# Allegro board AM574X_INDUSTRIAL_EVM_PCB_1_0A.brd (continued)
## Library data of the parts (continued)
C473-C475 = 1C_47uFCapacitor10V10%smd2917: User Part Number: P/N*; Tolerance: TOL*
C476 = 1C_2.2uFCapacitor10V20%smd0402: Tolerance: TOLERANCE; User Part Number: USERPART#
C554 C555 = C0402C104J4RACTU: Tolerance: TOLERANCE; signal model: 1C_0.1UFCAPACITOR16V10%0402_SM-_0.1uF
D1 = 1E_Diode_15ARect_rev45V
D2 = SMCJ5.0A
D3 D4 = Diode200mA250V_0
D5-D13 = 5988170107F
D14 D15 = Diode_500mA20V
D16-D19 D22 D23 = SM1210RGB
D20 = PMEG2010BELD,315
D24 D25 = TLVH431_0
F1 = 1P_Fuse_0
FB1-FB8 = HF70ACB201209-T
FB9-FB11 = MPZ1608S221ATA00
FB12 FB13 FB19 = 1L_FerBead_0
J1 = 2J_Conn_PwrJack_RAPC712
J1_1 = 2H_Header_4x1_female
J2 = 2C_Conn_LeadScrewDown_2pin
J3 J5 J6 J8 = 2J_ConnectorRJ45_10_100MbAMDIX
J4 J7 J38 = 2H_Header_5x1
J9 = 2H_Header12x2
J10 J12 = 2J_ConnectorRJ45_Gigabit
J14 = 2C_Conn_DSUB9F
J15 = 2C_Conn_microSD_8: User Part Number: X; Tolerance: X
J16 = 2C_Conn_FFC_0.5mm_32pos
J17 = 2C_Conn_FFC_0.5mm_6pos
J18 = 2C_Conn_JTAGMIPI_60pin
J19 J45 = USB
J21 = NPPN302AFCN-RC
J22 = 2C_PCIEConnector_10018783
J23 = 1932258-1
J24 = 2C_Conn_HDMI_TypeA
J37 = 2H_Header15x2_0.1in_Female
J39 = 2H_Header_3x1
J40-J44 J47 J49 J50 = 2H_Header_0
J46 = 2H_Header_4x1
L1 = 1L_0.7Asmd
L2 = DA2304-ALB
L3 L21 L24-L26 L34 L35 = 1L_NFM21PC474_EMIFilter_0
L11 L33 = ACM2012H-900-2P-T05
L12-L20 = SRP4012TA-1R0M
L22 = 1L_0.1Asmd
L28 = 1L_0.5Asmd
L29-L32 = 1M_DLW21SN900HQ2L_0: signal model: 1M_DLW21SN900HQ2L_DLW21SN900HQ2_DLW21SN900HQ2L
Q1-Q6 Q9-Q16 Q20-Q25 = 1Q_MOSFET_NChan_BSS138_0
Q7 Q8 = 1Q_MOSFET_PChan_FDT434P_1
Q26 Q27 = 1Q_MOSFET_PChan_FDT434P_0
R1_1 R97 R138 R141 R180 R218 R222 R278 R322 R472 R656 R742 = 1R_ZeroOhmResistor1/16W0603
R2 R2_1 R10 R18 R22 R32-R35 R37-R40 R45 R48 R107 R149 R153 R190 R233 R259 R299 R301 R306 R309 R343 R345 R352 R353 R364 R366 R397-R401 R412 R417 R420 R421 R425 R430-R432 R453-R468 R485 R494 R496 R498 R539 R542-R546 R548 R549 R551 R553 R561 R570 R571 R637 R644 R645 R649 R654 R741 R785 R786 R790 R791 R798-R800 R804 R805 R808 R810 R811 R814 R895 R896 R899 R900 R902 R912-R914 R917 = RMCF0402FT10K0
R3 R281-R292 R325-R336 R426 = RMCF0402FT22R1: signal model: 1R_22OHMRESISTOR1/16W1%0402_SM-_22
R4 R305 R349 = 1MOhmResistor1/16W0402
R5-R9 R13-R15 R19 R20 R29 R67 R77 R78 R89 R93 R105 R106 R112 R114 R115 R117-R119 R121 R122 R134 R148 R150 R151 R154 R160 R161 R172 R176 R178 R188 R189 R195-R199 R202 R203 R214 R230 R231 R234 R241 R243 R247 R248 R253 R254 R273-R275 R277 R294 R295 R300 R308 R312 R314 R338 R339 R351 R356 R358 R367 R369 R371 R377 R380 R381 R385 R387 R393 R394 R409-R411 R416 R418 R428 R451 R473-R478 R480-R483 R486 R487 R489 R492 R497 R499 R500 R514 R547 R550 R554 R555 R557-R559 R564 R566-R569 R572-R576 R582-R588 R590 R593 R594 R598 R600 R638 R643 R652 R653 R657-R666 R669-R679 R682-R686 R688-R692 R694 R698 R701 R703 R707 R710 R732-R740 R743 R744 R746-R753 R783 R787 R792 R794-R797 R802 R803 R809 R854 R861-R864 R905-R911 R915 R918-R927 R930-R934 = 1R_ZeroOhmResistor1/16W0402
R11 R429 R580 R581 R630-R633 R650 R655 R687 R788 R916 = 1R_100ohm1/16W1%SMD0402
R16 R17 R21 R304 R317 R319 R321 R348 R361 R363 = 1R_1KOhmResistor1/16W0402
R23-R28 R30 R31 R79-R88 R90-R92 R94-R96 R98 R123-R130 R132 R133 R135-R137 R139 R140 R142 R162-R171 R173-R175 R177 R179 R181 R204-R213 R215-R217 R219-R221 R223 R257 R258 R260-R265 R267 R269 R271 R402-R407 R565 R605-R628 R634-R636 R711-R728 = 1R_ZeroOhmResistor1/16W0402: signal model: 1R_ZEROOHMRESISTOR1/16W0402_SM-_0
R36 R648 R929 = 1R_18.2Kohm1/16W1%smd0402
R41 R42 R44 R754 R755 = 1R_240OhmResistor1/16W0402
R46 R47 R99-R102 R143-R146 R182-R185 R224-R227 R780 R781 = 1R_49.9OhmResistor1/16W0402
R49-R55 R57-R66 R68 R70-R75 R756-R779 R806 R807 = 1R_47ohm1/16W1%smd0402
R56 R245 R246 R251 R252 R255 R256 R280 R324 R419 R515 R577 R578 R591 R592 R595 R597 R599 R695 R697 R700 R704 R706 R709 R782 = 1R_100KOhmResistor1/16W0402
R69 R413 R784 = 1R_10ohm1/16W5%smd0402
R76 R104 R108-R111 R116 R120 R131 R152 R155-R159 R187 R191-R194 R200 R201 R232 R235-R238 R383 R384 R495 R556 R563 R579 = 1R_2.2KOhmResistor1/16W0402
R103 R147 R186 R228 = 1R_4.87Kohm1/16W1%smd0402
R113 = RMCF0402FT62R0
R239 R240 R242 R244 R249 R250 R386 R388-R392 R395 R396 R589 R596 R601-R604 R693 R696 R699 R702 R705 R708 = 1R_150ohm1/16W1%SMD0402
R276 R903 = RMCF0402FT22R1
R279 = RMCF0402JT1K50
R293 R296 R337 R340 R493 = 1R_220ohm1/10W1%smd0402
R297 R342 R422 R423 R433 R450 R484 R491 R560 R562 = 1R_4.7KOhmResistor1/16W0402
R298 R341 = 1R_12.1KohmResistor1/16W1%0402
R310 R313 R315 R354 R357 R359 R502 R504 = 1R_33ohmResistor1/16W5%0402
R368 R370 R372-R376 R378 = ERJ-6ENF1201V
R379 = ERJ-6ENF49R9V
R382 = 1R_25Kohm1/10W0.1%smd0603
R408 = 470Kohm1/16W1%SMD0402
R414 = 1R_47KOhmResistor1/16W0402
R415 = 1R_2OhmResistor1/10W1%0603
R424 = 1R_1.62MOhmResistor1/16W0402
R427 = 1R_180KOhmResistor1/16W0402
R434-R449 = 1R_18KohmResistor1/10W1%smd0402
R479 = 1R_12Kohm1/16W1%SMD0402
R503 = 1R_120ohm1/16W1%smd0402
R505-R513 = 1R_49.9KOhmResistor1/16W0402
R639 R640 R801 = LVK12R050DER
R641 = LVK12R010DER
R642 = LVK12R020FER
R646 = 1R_51Kohm1/16W1%smd0402
R647 = 1R_158Kohm1/16W1%smd0402
R680 = 1R_10KOhmResistor1/10W1%0402
R681 = 1R_19.6KohmResistor1/16W1%0402
R729-R731 = 1R_100ohm1/10W1%SMD0402
R793 R928 = 1R_20.5Kohm1/16W1%smd0402
R812 R813 = 1R_1MOhmResistor1/16W0402
R894 R898 = RMCF0402FT499R
R897 R901 = RMCF0402FT24K3
SCKT1 = AM57XX_SOCKET
SW1-SW3 = 2W_Switch_Pushbuttonsmd
TP1 TP1_1 TP8-TP11 = 2H_TestPointThroughHole
TP2 TP3 TP6 TP7 TP16-TP24 = 2H_Testpoint_SMD1mmCircle
U1 = AM5749ABZXEA
U1_1 = 1A_TLV70717
U2 U22 U26 U28 U35 U39 U47 U78 U96 U97 = SN74LVC1G07DCKRE4
U3 = TPS6590379ZWSR
U4 = 1A_S25FL256S_QSPI
U5-U7 U90 U91 = MT41K256M16HA-107
U8 U92 = TPS51200DRCT
U9 U13 U15 U17 = TLK105LRHBR
U18 = 1G_Haptics_Pico_0
U19 = SN74LVC1G04DCKRE4
U21 U24 = KSZ9031RNXCC
U23 U25 = 1A_CDCE913
U30 = TPD6E001RSER
U32 = TPS61081DRCT
U33 = 1A_CAT24C256W
U34 = SN74LVC1G00DCKR
U36 = TPD2E001DRLR
U37 = 1A_FT2232_2
U38 = 1A_93C56EEPROM2Kbit
U40 = 1A_IsoReg5V_R1Z-3.305HP
U41 = 1A_ISO1050
U43 = 1A_EMMC16G_S100
U44 = SN74LVC1G125DCKR
U45 = CDCM9102RHBT
U46 = TPD12S016PWR
U48-U50 U80-U84 U87 U88 = TPD1E10B06DPYR
U52 = TPS76650
U62 = TPS63010YFFR
U63 = 1A_SN74AVC4T245
U64 = TPD2EUSB30DRTR
U65 U75 = SN74AVC2T244DQMR
U66 = 1A_TPS2065D
U68-U71 U85 U98 = SN74LVC1G08DCKR
U72 = 1A_SN65HVS882
U73 = 1A_TPIC2810
U74 = 1A_ISO1176T
U76 = TPS71712DCKR
U77 = 1A_SN65HVD78
U79 = TPS61085DGKT
U86 = LP38693MP-ADJ/NOPB
U89 = 1A_TC358778XBG
U93 = TPD4S012DRYR
U94 = 1A_TPS2051BD
U95 = TPD4E05U06DQAR
X1 = CB3LV-3C-20M0000
Y1 = 1Y_Crystal20MHzSCM
Y2 = 1Y_Crystal16.384MHz
Y3 Y4 = 1Y_Crystal25MHzABM3_0
Y5 = 1Y_Crystal12MHzABM3_0
Y6 = MC-306 32.7680K-A0
Y7 = 1Y_Oscillator25MHzSMD

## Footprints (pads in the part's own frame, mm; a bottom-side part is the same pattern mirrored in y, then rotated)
7343
  rect 2.54x2.413 smd: 1(-3.2,0) 2(3.2,0)
ACM2012H
  rect 0.75x0.4 smd: 1(-0.925,0.4) 2(-0.925,-0.4) 3(0.925,-0.4) 4(0.925,0.4)
ASF_SMD3_2X5MM
  rect 1.5x1.7 smd: 1(-1.1,1.27) 2(-1.1,-1.27) 3(1.1,-1.27) 4(1.1,1.27)
BGA7X7-80-39M
  round 0.25 smd: A1(-2.925,2.925) A2(-2.275,2.925) A3(-1.625,2.925) A4(-0.975,2.925) A5(-0.325,2.925) A6(0.325,2.925) A7(0.975,2.925) A8(1.625,2.925) A9(2.275,2.925) A10(2.925,2.925) B1(-2.925,2.275) B2(-2.275,2.275) B3(-1.625,2.275) B4(-0.975,2.275) B5(-0.325,2.275) B6(0.325,2.275) B7(0.975,2.275) B8(1.625,2.275) B9(2.275,2.275) B10(2.925,2.275) C1(-2.925,1.625) C2(-2.275,1.625) C9(2.275,1.625) C10(2.925,1.625) D1(-2.925,0.975) D2(-2.275,0.975) D4(-0.975,0.975) D5(-0.325,0.975) D6(0.325,0.975) D7(0.975,0.975) D9(2.275,0.975) D10(2.925,0.975) E1(-2.925,0.325) E2(-2.275,0.325) E4(-0.975,0.325) E5(-0.325,0.325) E6(0.325,0.325) E7(0.975,0.325) E9(2.275,0.325) E10(2.925,0.325) F1(-2.925,-0.325) F2(-2.275,-0.325) F4(-0.975,-0.325) F5(-0.325,-0.325) F6(0.325,-0.325) F7(0.975,-0.325) F9(2.275,-0.325) F10(2.925,-0.325) G1(-2.925,-0.975) G2(-2.275,-0.975) G4(-0.975,-0.975) G5(-0.325,-0.975) G6(0.325,-0.975) G7(0.975,-0.975) G9(2.275,-0.975) G10(2.925,-0.975) H1(-2.925,-1.625) H2(-2.275,-1.625) H9(2.275,-1.625) H10(2.925,-1.625) J1(-2.925,-2.275) J2(-2.275,-2.275) J3(-1.625,-2.275) J4(-0.975,-2.275) J5(-0.325,-2.275) J6(0.325,-2.275) J7(0.975,-2.275) J8(1.625,-2.275) J9(2.275,-2.275) J10(2.925,-2.275) K1(-2.925,-2.925) K2(-2.275,-2.925) K3(-1.625,-2.925) K4(-0.975,-2.925) K5(-0.325,-2.925) K6(0.325,-2.925) K7(0.975,-2.925) K8(1.625,-2.925) K9(2.275,-2.925) K10(2.925,-2.925)
BGA9X14-96
  round 0.35 smd: A1(-3.2,6) A2(-2.4,6) A3(-1.6,6) A7(1.6,6) A8(2.4,6) A9(3.2,6) B1(-3.2,5.2) B2(-2.4,5.2) B3(-1.6,5.2) B7(1.6,5.2) B8(2.4,5.2) B9(3.2,5.2) C1(-3.2,4.4) C2(-2.4,4.4) C3(-1.6,4.4) C7(1.6,4.4) C8(2.4,4.4) C9(3.2,4.4) D1(-3.2,3.6) D2(-2.4,3.6) D3(-1.6,3.6) D7(1.6,3.6) D8(2.4,3.6) D9(3.2,3.6) E1(-3.2,2.8) E2(-2.4,2.8) E3(-1.6,2.8) E7(1.6,2.8) E8(2.4,2.8) E9(3.2,2.8) F1(-3.2,2) F2(-2.4,2) F3(-1.6,2) F7(1.6,2) F8(2.4,2) F9(3.2,2) G1(-3.2,1.2) G2(-2.4,1.2) G3(-1.6,1.2) G7(1.6,1.2) G8(2.4,1.2) G9(3.2,1.2) H1(-3.2,0.4) H2(-2.4,0.4) H3(-1.6,0.4) H7(1.6,0.4) H8(2.4,0.4) H9(3.2,0.4) J1(-3.2,-0.4) J2(-2.4,-0.4) J3(-1.6,-0.4) J7(1.6,-0.4) J8(2.4,-0.4) J9(3.2,-0.4) K1(-3.2,-1.2) K2(-2.4,-1.2) K3(-1.6,-1.2) K7(1.6,-1.2) K8(2.4,-1.2) K9(3.2,-1.2) L1(-3.2,-2) L2(-2.4,-2) L3(-1.6,-2) L7(1.6,-2) L8(2.4,-2) L9(3.2,-2) M1(-3.2,-2.8) M2(-2.4,-2.8) M3(-1.6,-2.8) M7(1.6,-2.8) M8(2.4,-2.8) M9(3.2,-2.8) N1(-3.2,-3.6) N2(-2.4,-3.6) N3(-1.6,-3.6) N7(1.6,-3.6) N8(2.4,-3.6) N9(3.2,-3.6) P1(-3.2,-4.4) P2(-2.4,-4.4) P3(-1.6,-4.4) P7(1.6,-4.4) P8(2.4,-4.4) P9(3.2,-4.4) R1(-3.2,-5.2) R2(-2.4,-5.2) R3(-1.6,-5.2) R7(1.6,-5.2) R8(2.4,-5.2) R9(3.2,-5.2) T1(-3.2,-6) T2(-2.4,-6) T3(-1.6,-6) T7(1.6,-6) T8(2.4,-6) T9(3.2,-6)
BGA11X13-153-39M
  round 0.25 smd: A1(-3.25,3.25) A2(-2.75,3.25) A3(-2.25,3.25) A4(-1.75,3.25) A5(-1.25,3.25) A6(-0.75,3.25) A7(-0.25,3.25) A8(0.25,3.25) A9(0.75,3.25) A10(1.25,3.25) A11(1.75,3.25) A12(2.25,3.25) A13(2.75,3.25) A14(3.25,3.25) B1(-3.25,2.75) B2(-2.75,2.75) B3(-2.25,2.75) B4(-1.75,2.75) B5(-1.25,2.75) B6(-0.75,2.75) B7(-0.25,2.75) B8(0.25,2.75) B9(0.75,2.75) B10(1.25,2.75) B11(1.75,2.75) B12(2.25,2.75) B13(2.75,2.75) B14(3.25,2.75) C1(-3.25,2.25) C2(-2.75,2.25) C3(-2.25,2.25) C4(-1.75,2.25) C5(-1.25,2.25) C6(-0.75,2.25) C7(-0.25,2.25) C8(0.25,2.25) C9(0.75,2.25) C10(1.25,2.25) C11(1.75,2.25) C12(2.25,2.25) C13(2.75,2.25) C14(3.25,2.25) D1(-3.25,1.75) D2(-2.75,1.75) D3(-2.25,1.75) D4(-1.75,1.75) D12(2.25,1.75) D13(2.75,1.75) D14(3.25,1.75) E1(-3.25,1.25) E2(-2.75,1.25) E3(-2.25,1.25) E5(-1.25,1.25) E6(-0.75,1.25) E7(-0.25,1.25) E8(0.25,1.25) E9(0.75,1.25) E10(1.25,1.25) E12(2.25,1.25) E13(2.75,1.25) E14(3.25,1.25) F1(-3.25,0.75) F2(-2.75,0.75) F3(-2.25,0.75) F5(-1.25,0.75) F10(1.25,0.75) F12(2.25,0.75) F13(2.75,0.75) F14(3.25,0.75) G1(-3.25,0.25) G2(-2.75,0.25) G3(-2.25,0.25) G5(-1.25,0.25) G10(1.25,0.25) G12(2.25,0.25) G13(2.75,0.25) G14(3.25,0.25) H1(-3.25,-0.25) H2(-2.75,-0.25) H3(-2.25,-0.25) H5(-1.25,-0.25) H10(1.25,-0.25) H12(2.25,-0.25) H13(2.75,-0.25) H14(3.25,-0.25) J1(-3.25,-0.75) J2(-2.75,-0.75) J3(-2.25,-0.75) J5(-1.25,-0.75) J10(1.25,-0.75) J12(2.25,-0.75) J13(2.75,-0.75) J14(3.25,-0.75) K1(-3.25,-1.25) K2(-2.75,-1.25) K3(-2.25,-1.25) K5(-1.25,-1.25) K6(-0.75,-1.25) K7(-0.25,-1.25) K8(0.25,-1.25) K9(0.75,-1.25) K10(1.25,-1.25) K12(2.25,-1.25) K13(2.75,-1.25) K14(3.25,-1.25) L1(-3.25,-1.75) L2(-2.75,-1.75) L3(-2.25,-1.75) L12(2.25,-1.75) L13(2.75,-1.75) L14(3.25,-1.75) M1(-3.25,-2.25) M2(-2.75,-2.25) M3(-2.25,-2.25) M4(-1.75,-2.25) M5(-1.25,-2.25) M6(-0.75,-2.25) M7(-0.25,-2.25) M8(0.25,-2.25) M9(0.75,-2.25) M10(1.25,-2.25) M11(1.75,-2.25) M12(2.25,-2.25) M13(2.75,-2.25) M14(3.25,-2.25) N1(-3.25,-2.75) N2(-2.75,-2.75) N3(-2.25,-2.75) N4(-1.75,-2.75) N5(-1.25,-2.75) N6(-0.75,-2.75) N7(-0.25,-2.75) N8(0.25,-2.75) N9(0.75,-2.75) N10(1.25,-2.75) N11(1.75,-2.75) N12(2.25,-2.75) N13(2.75,-2.75) N14(3.25,-2.75) P1(-3.25,-3.25) P2(-2.75,-3.25) P3(-2.25,-3.25) P4(-1.75,-3.25) P5(-1.25,-3.25) P6(-0.75,-3.25) P7(-0.25,-3.25) P8(0.25,-3.25) P9(0.75,-3.25) P10(1.25,-3.25) P11(1.75,-3.25) P12(2.25,-3.25) P13(2.75,-3.25) P14(3.25,-3.25)
BGA12X12-169-55M
  round 0.4 smd: A1(-4.8,4.8) A2(-4,4.8) A3(-3.2,4.8) A4(-2.4,4.8) A5(-1.6,4.8) A6(-0.8,4.8) A7(0,4.8) A8(0.8,4.8) A9(1.6,4.8) A10(2.4,4.8) A11(3.2,4.8) A12(4,4.8) A13(4.8,4.8) B1(-4.8,4) B2(-4,4) B3(-3.2,4) B4(-2.4,4) B5(-1.6,4) B6(-0.8,4) B7(0,4) B8(0.8,4) B9(1.6,4) B10(2.4,4) B11(3.2,4) B12(4,4) B13(4.8,4) C1(-4.8,3.2) C2(-4,3.2) C3(-3.2,3.2) C4(-2.4,3.2) C5(-1.6,3.2) C6(-0.8,3.2) C7(0,3.2) C8(0.8,3.2) C9(1.6,3.2) C10(2.4,3.2) C11(3.2,3.2) C12(4,3.2) C13(4.8,3.2) D1(-4.8,2.4) D2(-4,2.4) D3(-3.2,2.4) D4(-2.4,2.4) D5(-1.6,2.4) D6(-0.8,2.4) D7(0,2.4) D8(0.8,2.4) D9(1.6,2.4) D10(2.4,2.4) D11(3.2,2.4) D12(4,2.4) D13(4.8,2.4) E1(-4.8,1.6) E2(-4,1.6) E3(-3.2,1.6) E4(-2.4,1.6) E5(-1.6,1.6) E6(-0.8,1.6) E7(0,1.6) E8(0.8,1.6) E9(1.6,1.6) E10(2.4,1.6) E11(3.2,1.6) E12(4,1.6) E13(4.8,1.6) F1(-4.8,0.8) F2(-4,0.8) F3(-3.2,0.8) F4(-2.4,0.8) F5(-1.6,0.8) F6(-0.8,0.8) F7(0,0.8) F8(0.8,0.8) F9(1.6,0.8) F10(2.4,0.8) F11(3.2,0.8) F12(4,0.8) F13(4.8,0.8) G1(-4.8,0) G2(-4,0) G3(-3.2,0) G4(-2.4,0) G5(-1.6,0) G6(-0.8,0) G7(0,0) G8(0.8,0) G9(1.6,0) G10(2.4,0) G11(3.2,0) G12(4,0) G13(4.8,0) H1(-4.8,-0.8) H2(-4,-0.8) H3(-3.2,-0.8) H4(-2.4,-0.8) H5(-1.6,-0.8) H6(-0.8,-0.8) H7(0,-0.8) H8(0.8,-0.8) H9(1.6,-0.8) H10(2.4,-0.8) H11(3.2,-0.8) H12(4,-0.8) H13(4.8,-0.8) J1(-4.8,-1.6) J2(-4,-1.6) J3(-3.2,-1.6) J4(-2.4,-1.6) J5(-1.6,-1.6) J6(-0.8,-1.6) J7(0,-1.6) J8(0.8,-1.6) J9(1.6,-1.6) J10(2.4,-1.6) J11(3.2,-1.6) J12(4,-1.6) J13(4.8,-1.6) K1(-4.8,-2.4) K2(-4,-2.4) K3(-3.2,-2.4) K4(-2.4,-2.4) K5(-1.6,-2.4) K6(-0.8,-2.4) K7(0,-2.4) K8(0.8,-2.4) K9(1.6,-2.4) K10(2.4,-2.4) K11(3.2,-2.4) K12(4,-2.4) K13(4.8,-2.4) L1(-4.8,-3.2) L2(-4,-3.2) L3(-3.2,-3.2) L4(-2.4,-3.2) L5(-1.6,-3.2) L6(-0.8,-3.2) L7(0,-3.2) L8(0.8,-3.2) L9(1.6,-3.2) L10(2.4,-3.2) L11(3.2,-3.2) L12(4,-3.2) L13(4.8,-3.2) M1(-4.8,-4) M2(-4,-4) M3(-3.2,-4) M4(-2.4,-4) M5(-1.6,-4) M6(-0.8,-4) M7(0,-4) M8(0.8,-4) M9(1.6,-4) M10(2.4,-4) M11(3.2,-4) M12(4,-4) M13(4.8,-4) N1(-4.8,-4.8) N2(-4,-4.8) N3(-3.2,-4.8) N4(-2.4,-4.8) N5(-1.6,-4.8) N6(-0.8,-4.8) N7(0,-4.8) N8(0.8,-4.8) N9(1.6,-4.8) N10(2.4,-4.8) N11(3.2,-4.8) N12(4,-4.8) N13(4.8,-4.8)
BGA23X23-760-117M
  round 0.4 smd: A1(-10.8,10.8) A2(-10,10.8) A3(-9.2,10.8) A4(-8.4,10.8) A5(-7.6,10.8) A6(-6.8,10.8) A7(-6,10.8) A8(-5.2,10.8) A9(-4.4,10.8) A10(-3.6,10.8) A11(-2.8,10.8) A12(-2,10.8) A13(-1.2,10.8) A14(-0.4,10.8) A15(0.4,10.8) A16(1.2,10.8) A17(2,10.8) A18(2.8,10.8) A19(3.6,10.8) A20(4.4,10.8) A21(5.2,10.8) A22(6,10.8) A23(6.8,10.8) A24(7.6,10.8) A25(8.4,10.8) A26(9.2,10.8) A27(10,10.8) A28(10.8,10.8) AA1(-10.8,-5.2) AA2(-10,-5.2) AA3(-9.2,-5.2) AA4(-8.4,-5.2) AA5(-7.6,-5.2) AA6(-6.8,-5.2) AA7(-6,-5.2) AA8(-5.2,-5.2) AA9(-4.4,-5.2) AA10(-3.6,-5.2) AA11(-2.8,-5.2) AA12(-2,-5.2) AA13(-1.2,-5.2) AA14(-0.4,-5.2) AA15(0.4,-5.2) AA16(1.2,-5.2) AA17(2,-5.2) AA18(2.8,-5.2) AA19(3.6,-5.2) AA20(4.4,-5.2) AA21(5.2,-5.2) AA22(6,-5.2) AA23(6.8,-5.2) AA24(7.6,-5.2) AA25(8.4,-5.2) AA26(9.2,-5.2) AA27(10,-5.2) AA28(10.8,-5.2) AB1(-10.8,-6) AB2(-10,-6) AB3(-9.2,-6) AB4(-8.4,-6) AB5(-7.6,-6) AB6(-6.8,-6) AB7(-6,-6) AB8(-5.2,-6) AB9(-4.4,-6) AB10(-3.6,-6) AB11(-2.8,-6) AB12(-2,-6) AB13(-1.2,-6) AB14(-0.4,-6) AB15(0.4,-6) AB16(1.2,-6) AB17(2,-6) AB18(2.8,-6) AB19(3.6,-6) AB20(4.4,-6) AB21(5.2,-6) AB22(6,-6) AB23(6.8,-6) AB24(7.6,-6) AB25(8.4,-6) AB27(10,-6) AB28(10.8,-6) AC1(-10.8,-6.8) AC2(-10,-6.8) AC3(-9.2,-6.8) AC4(-8.4,-6.8) AC5(-7.6,-6.8) AC6(-6.8,-6.8) AC7(-6,-6.8) AC8(-5.2,-6.8) AC9(-4.4,-6.8) AC10(-3.6,-6.8) AC11(-2.8,-6.8) AC12(-2,-6.8) AC13(-1.2,-6.8) AC14(-0.4,-6.8) AC15(0.4,-6.8) AC16(1.2,-6.8) AC17(2,-6.8) AC18(2.8,-6.8) AC19(3.6,-6.8) AC20(4.4,-6.8) AC21(5.2,-6.8) AC22(6,-6.8) AC23(6.8,-6.8) AC24(7.6,-6.8) AC25(8.4,-6.8) AC26(9.2,-6.8) AC27(10,-6.8) AC28(10.8,-6.8) AD1(-10.8,-7.6) AD2(-10,-7.6) AD3(-9.2,-7.6) AD4(-8.4,-7.6) AD5(-7.6,-7.6) AD6(-6.8,-7.6) AD7(-6,-7.6) AD8(-5.2,-7.6) AD9(-4.4,-7.6) AD10(-3.6,-7.6) AD11(-2.8,-7.6) AD12(-2,-7.6) AD13(-1.2,-7.6) AD14(-0.4,-7.6) AD15(0.4,-7.6) AD16(1.2,-7.6) AD17(2,-7.6) AD18(2.8,-7.6) AD19(3.6,-7.6) AD20(4.4,-7.6) AD21(5.2,-7.6) AD22(6,-7.6) AD23(6.8,-7.6) AD24(7.6,-7.6) AD25(8.4,-7.6) AD26(9.2,-7.6) AD27(10,-7.6) AD28(10.8,-7.6) AE1(-10.8,-8.4) AE2(-10,-8.4) AE3(-9.2,-8.4) AE5(-7.6,-8.4) AE6(-6.8,-8.4) AE7(-6,-8.4) AE8(-5.2,-8.4) AE9(-4.4,-8.4) AE10(-3.6,-8.4) AE11(-2.8,-8.4) AE12(-2,-8.4) AE13(-1.2,-8.4) AE14(-0.4,-8.4) AE15(0.4,-8.4) AE16(1.2,-8.4) AE17(2,-8.4) AE18(2.8,-8.4) AE19(3.6,-8.4) AE20(4.4,-8.4) AE21(5.2,-8.4) AE22(6,-8.4) AE23(6.8,-8.4) AE24(7.6,-8.4) AE26(9.2,-8.4) AE27(10,-8.4) AE28(10.8,-8.4) AF1(-10.8,-9.2) AF2(-10,-9.2) AF3(-9.2,-9.2) AF4(-8.4,-9.2) AF5(-7.6,-9.2) AF6(-6.8,-9.2) AF8(-5.2,-9.2) AF9(-4.4,-9.2) AF11(-2.8,-9.2) AF12(-2,-9.2) AF14(-0.4,-9.2) AF15(0.4,-9.2) AF17(2,-9.2) AF18(2.8,-9.2) AF20(4.4,-9.2) AF21(5.2,-9.2) AF22(6,-9.2) AF23(6.8,-9.2) AF24(7.6,-9.2) AF25(8.4,-9.2) AF26(9.2,-9.2) AF27(10,-9.2) AF28(10.8,-9.2) AG1(-10.8,-10) AG2(-10,-10) AG3(-9.2,-10) AG4(-8.4,-10) AG5(-7.6,-10) AG6(-6.8,-10) AG7(-6,-10) AG8(-5.2,-10) AG9(-4.4,-10) AG10(-3.6,-10) AG11(-2.8,-10) AG12(-2,-10) AG13(-1.2,-10) AG14(-0.4,-10) AG15(0.4,-10) AG16(1.2,-10) AG17(2,-10) AG18(2.8,-10) AG19(3.6,-10) AG20(4.4,-10) AG21(5.2,-10) AG22(6,-10) AG23(6.8,-10) AG24(7.6,-10) AG25(8.4,-10) AG26(9.2,-10) AG27(10,-10) AG28(10.8,-10) AH1(-10.8,-10.8) AH2(-10,-10.8) AH3(-9.2,-10.8) AH4(-8.4,-10.8) AH5(-7.6,-10.8) AH6(-6.8,-10.8) AH7(-6,-10.8) AH8(-5.2,-10.8) AH9(-4.4,-10.8) AH10(-3.6,-10.8) AH11(-2.8,-10.8) AH12(-2,-10.8) AH13(-1.2,-10.8) AH14(-0.4,-10.8) AH15(0.4,-10.8) AH16(1.2,-10.8) AH17(2,-10.8) AH18(2.8,-10.8) AH19(3.6,-10.8) AH20(4.4,-10.8) AH21(5.2,-10.8) AH22(6,-10.8) AH23(6.8,-10.8) AH24(7.6,-10.8) AH25(8.4,-10.8) AH26(9.2,-10.8) AH27(10,-10.8) AH28(10.8,-10.8) B1(-10.8,10) B2(-10,10) B3(-9.2,10) B4(-8.4,10) B5(-7.6,10) B6(-6.8,10) B7(-6,10) B8(-5.2,10) B9(-4.4,10) B10(-3.6,10) B11(-2.8,10) B12(-2,10) B13(-1.2,10) B14(-0.4,10) B15(0.4,10) B16(1.2,10) B17(2,10) B18(2.8,10) B19(3.6,10) B20(4.4,10) B21(5.2,10) B22(6,10) B23(6.8,10) B24(7.6,10) B25(8.4,10) B26(9.2,10) B27(10,10) B28(10.8,10) C1(-10.8,9.2) C2(-10,9.2) C3(-9.2,9.2) C4(-8.4,9.2) C5(-7.6,9.2) C6(-6.8,9.2) C7(-6,9.2) C8(-5.2,9.2) C9(-4.4,9.2) C11(-2.8,9.2) C12(-2,9.2) C14(-0.4,9.2) C15(0.4,9.2) C17(2,9.2) C18(2.8,9.2) C20(4.4,9.2) C21(5.2,9.2) C23(6.8,9.2) C24(7.6,9.2) C25(8.4,9.2) C26(9.2,9.2) C27(10,9.2) C28(10.8,9.2) D1(-10.8,8.4) D2(-10,8.4) D3(-9.2,8.4) D5(-7.6,8.4) D6(-6.8,8.4) D7(-6,8.4) D8(-5.2,8.4) D9(-4.4,8.4) D10(-3.6,8.4) D11(-2.8,8.4) D12(-2,8.4) D13(-1.2,8.4) D14(-0.4,8.4) D15(0.4,8.4) D16(1.2,8.4) D17(2,8.4) D18(2.8,8.4) D19(3.6,8.4) D20(4.4,8.4) D21(5.2,8.4) D22(6,8.4) D23(6.8,8.4) D24(7.6,8.4) D26(9.2,8.4) D27(10,8.4) D28(10.8,8.4) E1(-10.8,7.6) E2(-10,7.6) E3(-9.2,7.6) E4(-8.4,7.6) E5(-7.6,7.6) E6(-6.8,7.6) E7(-6,7.6) E8(-5.2,7.6) E9(-4.4,7.6) E10(-3.6,7.6) E11(-2.8,7.6) E12(-2,7.6) E13(-1.2,7.6) E14(-0.4,7.6) E15(0.4,7.6) E16(1.2,7.6) E17(2,7.6) E18(2.8,7.6) E19(3.6,7.6) E20(4.4,7.6) E21(5.2,7.6) E22(6,7.6) E23(6.8,7.6) E24(7.6,7.6) E25(8.4,7.6) E26(9.2,7.6) E27(10,7.6) E28(10.8,7.6) F1(-10.8,6.8) F2(-10,6.8) F3(-9.2,6.8) F4(-8.4,6.8) F5(-7.6,6.8) F6(-6.8,6.8) F7(-6,6.8) F8(-5.2,6.8) F9(-4.4,6.8) F10(-3.6,6.8) F11(-2.8,6.8) F12(-2,6.8) F13(-1.2,6.8) F14(-0.4,6.8) F15(0.4,6.8) F16(1.2,6.8) F17(2,6.8) F18(2.8,6.8) F19(3.6,6.8) F20(4.4,6.8) F21(5.2,6.8) F22(6,6.8) F23(6.8,6.8) F24(7.6,6.8) F25(8.4,6.8) F26(9.2,6.8) F27(10,6.8) F28(10.8,6.8) G1(-10.8,6) G2(-10,6) G4(-8.4,6) G5(-7.6,6) G6(-6.8,6) G7(-6,6) G8(-5.2,6) G9(-4.4,6) G10(-3.6,6) G11(-2.8,6) G12(-2,6) G13(-1.2,6) G14(-0.4,6) G15(0.4,6) G16(1.2,6) G17(2,6) G18(2.8,6) G19(3.6,6) G20(4.4,6) G21(5.2,6) G22(6,6) G23(6.8,6) G24(7.6,6) G25(8.4,6) G26(9.2,6) G27(10,6) G28(10.8,6) H1(-10.8,5.2) H2(-10,5.2) H3(-9.2,5.2) H4(-8.4,5.2) H5(-7.6,5.2) H6(-6.8,5.2) H7(-6,5.2) H8(-5.2,5.2) H9(-4.4,5.2) H10(-3.6,5.2) H11(-2.8,5.2) H12(-2,5.2) H13(-1.2,5.2) H14(-0.4,5.2) H15(0.4,5.2) H16(1.2,5.2) H17(2,5.2) H18(2.8,5.2) H19(3.6,5.2) H20(4.4,5.2) H21(5.2,5.2) H22(6,5.2) H23(6.8,5.2) H24(7.6,5.2) H25(8.4,5.2) H26(9.2,5.2) H27(10,5.2) H28(10.8,5.2) J1(-10.8,4.4) J2(-10,4.4) J3(-9.2,4.4) J4(-8.4,4.4) J5(-7.6,4.4) J6(-6.8,4.4) J7(-6,4.4) J8(-5.2,4.4) J9(-4.4,4.4) J10(-3.6,4.4) J11(-2.8,4.4) J12(-2,4.4) J13(-1.2,4.4) J14(-0.4,4.4) J15(0.4,4.4) J16(1.2,4.4) J17(2,4.4) J18(2.8,4.4) J19(3.6,4.4) J20(4.4,4.4) J21(5.2,4.4) J22(6,4.4) J23(6.8,4.4) J24(7.6,4.4) J25(8.4,4.4) J26(9.2,4.4) J27(10,4.4) J28(10.8,4.4) K1(-10.8,3.6) K2(-10,3.6) K4(-8.4,3.6) K5(-7.6,3.6) K6(-6.8,3.6) K7(-6,3.6) K8(-5.2,3.6) K9(-4.4,3.6) K10(-3.6,3.6) K11(-2.8,3.6) K12(-2,3.6) K13(-1.2,3.6) K14(-0.4,3.6) K15(0.4,3.6) K16(1.2,3.6) K17(2,3.6) K18(2.8,3.6) K19(3.6,3.6) K20(4.4,3.6) K21(5.2,3.6) K22(6,3.6) K23(6.8,3.6) K24(7.6,3.6) K25(8.4,3.6) K27(10,3.6) K28(10.8,3.6) L1(-10.8,2.8) L2(-10,2.8) L3(-9.2,2.8) L4(-8.4,2.8) L5(-7.6,2.8) L6(-6.8,2.8) L7(-6,2.8) L8(-5.2,2.8) L9(-4.4,2.8) L10(-3.6,2.8) L11(-2.8,2.8) L12(-2,2.8) L13(-1.2,2.8) L14(-0.4,2.8) L15(0.4,2.8) L16(1.2,2.8) L17(2,2.8) L18(2.8,2.8) L19(3.6,2.8) L20(4.4,2.8) L21(5.2,2.8) L22(6,2.8) L23(6.8,2.8) L24(7.6,2.8) L25(8.4,2.8) L26(9.2,2.8) L27(10,2.8) L28(10.8,2.8) M1(-10.8,2) M2(-10,2) M3(-9.2,2) M4(-8.4,2) M5(-7.6,2) M6(-6.8,2) M7(-6,2) M8(-5.2,2) M9(-4.4,2) M10(-3.6,2) M11(-2.8,2) M12(-2,2) M13(-1.2,2) M14(-0.4,2) M15(0.4,2) M16(1.2,2) M17(2,2) M18(2.8,2) M19(3.6,2) M20(4.4,2) M21(5.2,2) M22(6,2) M23(6.8,2) M24(7.6,2) M25(8.4,2) M26(9.2,2) M27(10,2) M28(10.8,2) N1(-10.8,1.2) N2(-10,1.2) N4(-8.4,1.2) N5(-7.6,1.2) N6(-6.8,1.2) N7(-6,1.2) N8(-5.2,1.2) N9(-4.4,1.2) N10(-3.6,1.2) N11(-2.8,1.2) N12(-2,1.2) N13(-1.2,1.2) N14(-0.4,1.2) N15(0.4,1.2) N16(1.2,1.2) N17(2,1.2) N18(2.8,1.2) N19(3.6,1.2) N20(4.4,1.2) N21(5.2,1.2) N22(6,1.2) N23(6.8,1.2) N24(7.6,1.2) N25(8.4,1.2) N27(10,1.2) N28(10.8,1.2) P1(-10.8,0.4) P2(-10,0.4) P3(-9.2,0.4) P4(-8.4,0.4) P5(-7.6,0.4) P6(-6.8,0.4) P7(-6,0.4) P8(-5.2,0.4) P9(-4.4,0.4) P10(-3.6,0.4) P11(-2.8,0.4) P12(-2,0.4) P13(-1.2,0.4) P14(-0.4,0.4) P15(0.4,0.4) P16(1.2,0.4) P17(2,0.4) P18(2.8,0.4) P19(3.6,0.4) P20(4.4,0.4) P21(5.2,0.4) P22(6,0.4) P23(6.8,0.4) P24(7.6,0.4) P25(8.4,0.4) P26(9.2,0.4) P27(10,0.4) P28(10.8,0.4) R1(-10.8,-0.4) R2(-10,-0.4) R3(-9.2,-0.4) R4(-8.4,-0.4) R5(-7.6,-0.4) R6(-6.8,-0.4) R7(-6,-0.4) R8(-5.2,-0.4) R9(-4.4,-0.4) R10(-3.6,-0.4) R11(-2.8,-0.4) R12(-2,-0.4) R13(-1.2,-0.4) R14(-0.4,-0.4) R15(0.4,-0.4) R16(1.2,-0.4) R17(2,-0.4) R18(2.8,-0.4) R19(3.6,-0.4) R20(4.4,-0.4) R21(5.2,-0.4) R22(6,-0.4) R23(6.8,-0.4) R24(7.6,-0.4) R25(8.4,-0.4) R26(9.2,-0.4) R27(10,-0.4) R28(10.8,-0.4) T1(-10.8,-1.2) T2(-10,-1.2) T4(-8.4,-1.2) T5(-7.6,-1.2) T6(-6.8,-1.2) T7(-6,-1.2) T8(-5.2,-1.2) T9(-4.4,-1.2) T10(-3.6,-1.2) T11(-2.8,-1.2) T12(-2,-1.2) T13(-1.2,-1.2) T14(-0.4,-1.2) T15(0.4,-1.2) T16(1.2,-1.2) T17(2,-1.2) T18(2.8,-1.2) T19(3.6,-1.2) T20(4.4,-1.2) T21(5.2,-1.2) T22(6,-1.2) T23(6.8,-1.2) T24(7.6,-1.2) T25(8.4,-1.2) T27(10,-1.2) T28(10.8,-1.2) U1(-10.8,-2) U2(-10,-2) U3(-9.2,-2) U4(-8.4,-2) U5(-7.6,-2) U6(-6.8,-2) U7(-6,-2) U8(-5.2,-2) U9(-4.4,-2) U10(-3.6,-2) U11(-2.8,-2) U12(-2,-2) U13(-1.2,-2) U14(-0.4,-2) U15(0.4,-2) U16(1.2,-2) U17(2,-2) U18(2.8,-2) U19(3.6,-2) U20(4.4,-2) U21(5.2,-2) U22(6,-2) U23(6.8,-2) U24(7.6,-2) U25(8.4,-2) U26(9.2,-2) U27(10,-2) U28(10.8,-2) V1(-10.8,-2.8) V2(-10,-2.8) V3(-9.2,-2.8) V4(-8.4,-2.8) V5(-7.6,-2.8) V6(-6.8,-2.8) V7(-6,-2.8) V8(-5.2,-2.8) V9(-4.4,-2.8) V10(-3.6,-2.8) V11(-2.8,-2.8) V12(-2,-2.8) V13(-1.2,-2.8) V14(-0.4,-2.8) V15(0.4,-2.8) V16(1.2,-2.8) V17(2,-2.8) V18(2.8,-2.8) V19(3.6,-2.8) V20(4.4,-2.8) V21(5.2,-2.8) V22(6,-2.8) V23(6.8,-2.8) V24(7.6,-2.8) V25(8.4,-2.8) V26(9.2,-2.8) V27(10,-2.8) V28(10.8,-2.8) W1(-10.8,-3.6) W2(-10,-3.6) W4(-8.4,-3.6) W5(-7.6,-3.6) W6(-6.8,-3.6) W7(-6,-3.6) W8(-5.2,-3.6) W9(-4.4,-3.6) W10(-3.6,-3.6) W11(-2.8,-3.6) W12(-2,-3.6) W13(-1.2,-3.6) W14(-0.4,-3.6) W15(0.4,-3.6) W16(1.2,-3.6) W17(2,-3.6) W18(2.8,-3.6) W19(3.6,-3.6) W20(4.4,-3.6) W21(5.2,-3.6) W22(6,-3.6) W23(6.8,-3.6) W24(7.6,-3.6) W25(8.4,-3.6) W27(10,-3.6) W28(10.8,-3.6) Y1(-10.8,-4.4) Y2(-10,-4.4) Y3(-9.2,-4.4) Y4(-8.4,-4.4) Y5(-7.6,-4.4) Y6(-6.8,-4.4) Y7(-6,-4.4) Y8(-5.2,-4.4) Y9(-4.4,-4.4) Y10(-3.6,-4.4) Y11(-2.8,-4.4) Y12(-2,-4.4) Y13(-1.2,-4.4) Y14(-0.4,-4.4) Y15(0.4,-4.4) Y16(1.2,-4.4) Y17(2,-4.4) Y18(2.8,-4.4) Y19(3.6,-4.4) Y20(4.4,-4.4) Y21(5.2,-4.4) Y22(6,-4.4) Y23(6.8,-4.4) Y24(7.6,-4.4) Y25(8.4,-4.4) Y26(9.2,-4.4) Y27(10,-4.4) Y28(10.8,-4.4)
CN_10018783-11000TLF
  round 2.35 hole 2.35 unplated: (11.65,-1.25) (20.8,-1.25)
  rect 1.228x1.228 hole 0.72: A1(0,0)
  round 1.228 hole 0.72: A2(1,2) A3(2,0) A4(3,2) A5(4,0) A6(5,2) A7(6,0) A8(7,2) A9(8,0) A10(9,2) A11(10,0) A12(13,2) A13(14,0) A14(15,2) A15(16,0) A16(17,2) A17(18,0) A18(19,2) B1(0,-2.5) B2(1,-4.5) B3(2,-2.5) B4(3,-4.5) B5(4,-2.5) B6(5,-4.5) B7(6,-2.5) B8(7,-4.5) B9(8,-2.5) B10(9,-4.5) B11(10,-2.5) B12(13,-4.5) B13(14,-2.5) B14(15,-4.5) B15(16,-2.5) B16(17,-4.5) B17(18,-2.5) B18(19,-4.5)
CN_LPAF3102NL
  rect 1.168x1.168 hole 0.711: 1(0,0)
  round 1.168 hole 0.711: 2(2.5,0) 3(4.5,0) 4(7,0) 5(7.5,1.5) 6(5.5,1.5) 7(3.5,1.5) 8(1.5,1.5) 9(-0.5,1.5)
  round 2.921 hole 2.286: S1(-3.07,-2) S2(10.07,-2)
CNQSH030DA
  round 1.143 hole 1.143 unplated: (-10.065,2.67) (10.065,2.67)
  rect 0.279x2.286 smd: 1(-7.25,-2.865) 2(-7.25,2.865) 3(-6.75,-2.865) 4(-6.75,2.865) 5(-6.25,-2.865) 6(-6.25,2.865) 7(-5.75,-2.865) 8(-5.75,2.865) 9(-5.25,-2.865) 10(-5.25,2.865) 11(-4.75,-2.865) 12(-4.75,2.865) 13(-4.25,-2.865) 14(-4.25,2.865) 15(-3.75,-2.865) 16(-3.75,2.865) 17(-3.25,-2.865) 18(-3.25,2.865) 19(-2.75,-2.865) 20(-2.75,2.865) 21(-2.25,-2.865) 22(-2.25,2.865) 23(-1.75,-2.865) 24(-1.75,2.865) 25(-1.25,-2.865) 26(-1.25,2.865) 27(-0.75,-2.865) 28(-0.75,2.865) 29(-0.25,-2.865) 30(-0.25,2.865) 31(0.25,-2.865) 32(0.25,2.865) 33(0.75,-2.865) 34(0.75,2.865) 35(1.25,-2.865) 36(1.25,2.865) 37(1.75,-2.865) 38(1.75,2.865) 39(2.25,-2.865) 40(2.25,2.865) 41(2.75,-2.865) 42(2.75,2.865) 43(3.25,-2.865) 44(3.25,2.865) 45(3.75,-2.865) 46(3.75,2.865) 47(4.25,-2.865) 48(4.25,2.865) 49(4.75,-2.865) 50(4.75,2.865) 51(5.25,-2.865) 52(5.25,2.865) 53(5.75,-2.865) 54(5.75,2.865) 55(6.25,-2.865) 56(6.25,2.865) 57(6.75,-2.865) 58(6.75,2.865) 59(7.25,-2.865) 60(7.25,2.865)
  rect 2.54x0.432 smd: 61(-8.065,0) 64(8.065,0)
  rect 4.699x0.432 smd: 62(-3.175,0) 63(3.175,0)
CNRJ45-1X1WLED
  round 3.2 hole 3.2 unplated: (-1.27,-6.35) (10.16,-6.35)
  rect 1.525x1.525 hole 0.89: 1(0,0)
  round 1.525 hole 0.89: 2(1.27,2.54) 3(2.54,0) 4(3.81,2.54) 5(5.08,0) 6(6.35,2.54) 7(7.62,0) 8(8.89,2.54)
  round 1.655 hole 1.02: 9(11.17,-8.89) 10(11.17,-10.92) 11(-2.28,-8.89) 12(-2.28,-10.92)
  round 2.337 hole 1.702: SHLD1(-3.43,-3.3) SHLD2(12.32,-3.3)
CNRJ45-1X1WLED-598M
  round 3.2 hole 3.2 unplated: (0,-8.89) (11.43,-8.89)
  rect 1.525x1.525 hole 0.89: 1(0,0)
  round 1.525 hole 0.89: 2(1.27,-2.54) 3(2.54,0) 4(3.81,-2.54) 5(5.08,0) 6(6.35,-2.54) 7(7.62,0) 8(8.89,-2.54) 9(10.16,0) 10(11.43,-2.54)
  round 1.655 hole 1.02: 11(12.44,-11.43) 12(12.44,-13.46) 13(-1.01,-11.43) 14(-1.01,-13.46)
  round 2.337 hole 1.702: SHLD1(-2.035,-5.84) SHLD2(13.465,-5.84)
CNXF2L-0625-1A
  rect 0.25x1 smd: 1(-1.25,1.95) 2(-0.75,1.95) 3(-0.25,1.95) 4(0.25,1.95) 5(0.75,1.95) 6(1.25,1.95)
  rect 1x1.34 smd: MNT1(-3.64,0.23) MNT2(3.64,0.23)
CNXF2M-3215-1A
  rect 0.254x1.092 smd: 1(-7.75,1.95) 2(-7.25,1.95) 3(-6.75,1.95) 4(-6.25,1.95) 5(-5.75,1.95) 6(-5.25,1.95) 7(-4.75,1.95) 8(-4.25,1.95) 9(-3.75,1.95) 10(-3.25,1.95) 11(-2.75,1.95) 12(-2.25,1.95) 13(-1.75,1.95) 14(-1.25,1.95) 15(-0.75,1.95) 16(-0.25,1.95) 17(0.25,1.95) 18(0.75,1.95) 19(1.25,1.95) 20(1.75,1.95) 21(2.25,1.95) 22(2.75,1.95) 23(3.25,1.95) 24(3.75,1.95) 25(4.25,1.95) 26(4.75,1.95) 27(5.25,1.95) 28(5.75,1.95) 29(6.25,1.95) 30(6.75,1.95) 31(7.25,1.95) 32(7.75,1.95)
  rect 1.7x1.5 smd: MNT1(-9.4,-1.95) MNT2(9.4,-1.95)
CONN_OSTTC02
  round 1.778 hole 1.27: 1(0,0) 2(5.08,0)
DA2304
  rect 1.7x1.6 smd: 1(-5.4,3) 2(-5.4,1) 3(-5.4,-1) 4(-5.4,-3) 5(5.4,-3) 6(5.4,-1) 7(5.4,1) 8(5.4,3)
DFN1006D-2
  rect 0.5x0.7 smd: 1(-0.4,0) 2(0.4,0)
DRCPSO_10PIN
  rect 0.305x1.092 smd: 1(-1,-1.625) 2(-0.5,-1.625) 3(0,-1.625) 4(0.5,-1.625) 5(1,-1.625) 6(1,1.625) 7(0.5,1.625) 8(0,1.625) 9(-0.5,1.625) 10(-1,1.625)
  custom 0.412x0.412 smd: 11(0,0)
FILT-DLW21S
  rect 0.9x0.4 smd: 1(-0.85,-0.4) 2(0.85,-0.4) 3(0.85,0.4) 4(-0.85,0.4)
FILT-NFM21PC
  rect 0.6x0.8 smd: 1(-1,0) 3(1,0)
  rect 0.6x1.9 smd: 2(0,0)
FUSE-0154
  rect 4.242x3.81 smd: 1(-3.188,0) 2(3.188,0)
HDR1X4-330M
  rect 1.778x1.778 hole 1.143: 1(0,0)
  round 1.778 hole 1.143: 2(0,-2.54) 3(0,-5.08) 4(0,-7.62)
HDR2X12
  rect 1.785x1.785 hole 1.15: 1(0,0)
  round 1.785 hole 1.15: 2(2.54,0) 3(0,-2.54) 4(2.54,-2.54) 5(0,-5.08) 6(2.54,-5.08) 7(0,-7.62) 8(2.54,-7.62) 9(0,-10.16) 10(2.54,-10.16) 11(0,-12.7) 12(2.54,-12.7) 13(0,-15.24) 14(2.54,-15.24) 15(0,-17.78) 16(2.54,-17.78) 17(0,-20.32) 18(2.54,-20.32) 19(0,-22.86) 20(2.54,-22.86) 21(0,-25.4) 22(2.54,-25.4) 23(0,-27.94) 24(2.54,-27.94)
HDR2X15-344M
  rect 1.655x1.655 hole 1.02: 1(0,0)
  round 1.655 hole 1.02: 2(0,2.54) 3(2.54,0) 4(2.54,2.54) 5(5.08,0) 6(5.08,2.54) 7(7.62,0) 8(7.62,2.54) 9(10.16,0) 10(10.16,2.54) 11(12.7,0) 12(12.7,2.54) 13(15.24,0) 14(15.24,2.54) 15(17.78,0) 16(17.78,2.54) 17(20.32,0) 18(20.32,2.54) 19(22.86,0) 20(22.86,2.54) 21(25.4,0) 22(25.4,2.54) 23(27.94,0) 24(27.94,2.54) 25(30.48,0) 26(30.48,2.54) 27(33.02,0) 28(33.02,2.54) 29(35.56,0) 30(35.56,2.54)
HDR2X30-2MM-177M
  rect 1.524x1.524 hole 0.838: 1(0,0)
  round 1.524 hole 0.838: 2(0,2) 3(2,0) 4(2,2) 5(4,0) 6(4,2) 7(6,0) 8(6,2) 9(8,0) 10(8,2) 11(10,0) 12(10,2) 13(12,0) 14(12,2) 15(14,0) 16(14,2) 17(16,0) 18(16,2) 19(18,0) 20(18,2) 21(20,0) 22(20,2) 23(22,0) 24(22,2) 25(24,0) 26(24,2) 27(26,0) 28(26,2) 29(28,0) 30(28,2) 31(30,0) 32(30,2) 33(32,0) 34(32,2) 35(34,0) 36(34,2) 37(36,0) 38(36,2) 39(38,0) 40(38,2) 41(40,0) 42(40,2) 43(42,0) 44(42,2) 45(44,0) 46(44,2) 47(46,0) 48(46,2) 49(48,0) 50(48,2) 51(50,0) 52(50,2) 53(52,0) 54(52,2) 55(54,0) 56(54,2) 57(56,0) 58(56,2) 59(58,0) 60(58,2)
HDR4X1RA-108M
  rect 1.651x1.651 hole 1.016: 1(0,0)
  round 1.651 hole 1.016: 2(0,-2.54) 3(0,-5.08) 4(0,-7.62)
HEADER_2X1
  rect 1.778x1.778 hole 1.016: 1(0,0)
  round 1.778 hole 1.016: 2(0,2.54)
HEADER_3X1
  rect 1.651x1.651 hole 1.016: 1(0,0)
  round 1.651 hole 1.016: 2(2.54,0) 3(5.08,0)
HEADER_5X1
  rect 1.778x1.778 hole 1.016: 1(0,0)
  round 1.778 hole 1.016: 2(2.54,0) 3(5.08,0) 4(7.62,0) 5(10.16,0)
HF70ACB201209
  rect 1x1 smd: 1(-1,0) 2(1,0)
IND_IHLP1616AB
  rect 1.65x2.3 smd: 1(-1.65,0) 2(1.65,0)
LED-SM1210
  rect 1.5x1 smd: 1(-1.75,0.7) 2(-1.75,-0.7) 3(1.75,0.7) 4(1.75,-0.7)
LQFP64PIN
  rect 1.5x0.3 smd: 1(-5.7,3.75) 2(-5.7,3.25) 3(-5.7,2.75) 4(-5.7,2.25) 5(-5.7,1.75) 6(-5.7,1.25) 7(-5.7,0.75) 8(-5.7,0.25) 9(-5.7,-0.25) 10(-5.7,-0.75) 11(-5.7,-1.25) 12(-5.7,-1.75) 13(-5.7,-2.25) 14(-5.7,-2.75) 15(-5.7,-3.25) 16(-5.7,-3.75) 33(5.7,-3.75) 34(5.7,-3.25) 35(5.7,-2.75) 36(5.7,-2.25) 37(5.7,-1.75) 38(5.7,-1.25) 39(5.7,-0.75) 40(5.7,-0.25) 41(5.7,0.25) 42(5.7,0.75) 43(5.7,1.25) 44(5.7,1.75) 45(5.7,2.25) 46(5.7,2.75) 47(5.7,3.25) 48(5.7,3.75)
  rect 0.3x1.5 smd: 17(-3.75,-5.7) 18(-3.25,-5.7) 19(-2.75,-5.7) 20(-2.25,-5.7) 21(-1.75,-5.7) 22(-1.25,-5.7) 23(-0.75,-5.7) 24(-0.25,-5.7) 25(0.25,-5.7) 26(0.75,-5.7) 27(1.25,-5.7) 28(1.75,-5.7) 29(2.25,-5.7) 30(2.75,-5.7) 31(3.25,-5.7) 32(3.75,-5.7) 49(3.75,5.7) 50(3.25,5.7) 51(2.75,5.7) 52(2.25,5.7) 53(1.75,5.7) 54(1.25,5.7) 55(0.75,5.7) 56(0.25,5.7) 57(-0.25,5.7) 58(-0.75,5.7) 59(-1.25,5.7) 60(-1.75,5.7) 61(-2.25,5.7) 62(-2.75,5.7) 63(-3.25,5.7) 64(-3.75,5.7)
MBR0520L
  rect 0.914x1.219 smd: 1(1.651,0) 2(-1.651,0)
MC-306
  rect 1.3x1.9 smd: 1(-2.75,-1.6) 2(2.75,-1.6) 3(2.75,1.6) 4(-2.75,1.6)
MSOP3X3-8-43M
  rect 1.35x0.4 smd: 1(-2.225,0.975) 2(-2.225,0.325) 3(-2.225,-0.325) 4(-2.225,-0.975) 5(2.225,-0.975) 6(2.225,-0.325) 7(2.225,0.325) 8(2.225,0.975)
NORCOMP_DB9F_SMD
  round 1.499 hole 1.499 unplated: (-7.95,-0.66) (7.95,-0.66)
  rect 0.8x3.5 smd: 1(-5.537,0) 2(-2.769,0) 3(0,0) 4(2.769,0) 5(5.537,0) 6(-4.153,0) 7(-1.384,0) 8(1.384,0) 9(4.153,0)
  round 4.572 hole 3.048: 10(-12.497,-0.66) 11(12.497,-0.66)
OSC7X5-71M
  rect 1.8x2 smd: 1(-2.54,-2) 2(2.54,-2) 3(2.54,2) 4(-2.54,2)
PICO_304-100
  rect 1.5x1.5 hole 0.762: 1(0,0)
  round 1.5 hole 0.762: 2(-2.3,0)
  round 2.75 hole 1.092: M1(-1.15,-2.7) M2(-1.15,-10.5)
PW_24PIN_TSSOP
  rect 0.356x1.524 smd: 1(-3.575,-2.96) 2(-2.925,-2.96) 3(-2.275,-2.96) 4(-1.625,-2.96) 5(-0.975,-2.96) 6(-0.325,-2.96) 7(0.325,-2.96) 8(0.975,-2.96) 9(1.625,-2.96) 10(2.275,-2.96) 11(2.925,-2.96) 12(3.575,-2.96) 13(3.575,2.96) 14(2.925,2.96) 15(2.275,2.96) 16(1.625,2.96) 17(0.975,2.96) 18(0.325,2.96) 19(-0.325,2.96) 20(-0.975,2.96) 21(-1.625,2.96) 22(-2.275,2.96) 23(-2.925,2.96) 24(-3.575,2.96)
QFN5X5-32-39M
  custom 0.075x0.075 smd: 1(-2.475,1.75) 2(-2.475,1.25) 3(-2.475,0.75) 4(-2.475,0.25) 5(-2.475,-0.25) 6(-2.475,-0.75) 7(-2.475,-1.25) 8(-2.475,-1.75) 9(-1.75,-2.475) 10(-1.25,-2.475) 11(-0.75,-2.475) 12(-0.25,-2.475) 13(0.25,-2.475) 14(0.75,-2.475) 15(1.25,-2.475) 16(1.75,-2.475) 17(2.475,-1.75) 18(2.475,-1.25) 19(2.475,-0.75) 20(2.475,-0.25) 21(2.475,0.25) 22(2.475,0.75) 23(2.475,1.25) 24(2.475,1.75) 25(1.75,2.475) 26(1.25,2.475) 27(0.75,2.475) 28(0.25,2.475) 29(-0.25,2.475) 30(-0.75,2.475) 31(-1.25,2.475) 32(-1.75,2.475)
  rect 3x3 smd: TPAD(0,0)
QFN5X5-32TI-39M
  custom 0.07x0.07 smd: 1(-2.475,1.75) 2(-2.475,1.25) 3(-2.475,0.75) 4(-2.475,0.25) 5(-2.475,-0.25) 6(-2.475,-0.75) 7(-2.475,-1.25) 8(-2.475,-1.75) 9(-1.75,-2.475) 10(-1.25,-2.475) 11(-0.75,-2.475) 12(-0.25,-2.475) 13(0.25,-2.475) 14(0.75,-2.475) 15(1.25,-2.475) 16(1.75,-2.475) 17(2.475,-1.75) 18(2.475,-1.25) 19(2.475,-0.75) 20(2.475,-0.25) 21(2.475,0.25) 22(2.475,0.75) 23(2.475,1.25) 24(2.475,1.75) 25(1.75,2.475) 26(1.25,2.475) 27(0.75,2.475) 28(0.25,2.475) 29(-0.25,2.475) 30(-0.75,2.475) 31(-1.25,2.475) 32(-1.75,2.475)
  rect 3.45x3.45 smd: TPAD(0,0)
QFN7X7-48
  rect 0.85x0.28 smd: 1(-3.475,2.75) 2(-3.475,2.25) 3(-3.475,1.75) 4(-3.475,1.25) 5(-3.475,0.75) 6(-3.475,0.25) 7(-3.475,-0.25) 8(-3.475,-0.75) 9(-3.475,-1.25) 10(-3.475,-1.75) 11(-3.475,-2.25) 12(-3.475,-2.75) 25(3.475,-2.75) 26(3.475,-2.25) 27(3.475,-1.75) 28(3.475,-1.25) 29(3.475,-0.75) 30(3.475,-0.25) 31(3.475,0.25) 32(3.475,0.75) 33(3.475,1.25) 34(3.475,1.75) 35(3.475,2.25) 36(3.475,2.75)
  rect 0.28x0.85 smd: 13(-2.75,-3.475) 14(-2.25,-3.475) 15(-1.75,-3.475) 16(-1.25,-3.475) 17(-0.75,-3.475) 18(-0.25,-3.475) 19(0.25,-3.475) 20(0.75,-3.475) 21(1.25,-3.475) 22(1.75,-3.475) 23(2.25,-3.475) 24(2.75,-3.475) 37(2.75,3.475) 38(2.25,3.475) 39(1.75,3.475) 40(1.25,3.475) 41(0.75,3.475) 42(0.25,3.475) 43(-0.25,3.475) 44(-0.75,3.475) 45(-1.25,3.475) 46(-1.75,3.475) 47(-2.25,3.475) 48(-2.75,3.475)
  rect 5.15x5.15 smd: 49(0,0)
RAPC712
  round 4.064 hole 3.556: 1(0,0)
  round 3.683 hole 3.048: 2(-2.997,-4.801) 3(-6.248,0)
SC70-5-43M
  rect 0.95x0.4 smd: 1(-1.075,0.65) 2(-1.075,0) 3(-1.075,-0.65) 4(1.075,-0.65) 5(1.075,0.65)
SCK-SG-BGA-6334
  round 1.75 hole 1.75 unplated: (-12.863,12.863) (12.863,-12.863)
  round 0.85 hole 0.85 unplated: (-12.863,-7.783) (12.863,10.323)
  round 2.385 hole 1.75: MCH2(12.863,12.863) MCH4(-12.863,-12.863)
SD-MICRO-SCHA5B0300
  rect 0.914x0.457 smd: 1(-7.257,0) 2(-7.257,-0.7) 3(-7.257,-1.4) 4(-7.257,-2.1) 5(7.257,-2.1) 6(7.257,-1.4) 7(7.257,-0.7) 8(7.257,0)
  rect 0.508x0.889 smd: 9(3.775,9.989) 10(-5.975,9.989)
  rect 0.889x2.007 smd: 11(-7.25,7.635) 12(7.25,6.335)
  rect 1.118x1.524 smd: 13(-7.196,-3.365) 14(7.196,-3.365)
  rect 1.194x1.092 smd: 15(-3.425,10.488) 16(2.575,10.488)
SK1545
  rect 1.778x5.08 smd: 1(-3.302,0) 2(3.302,0)
SM-7351-CAP-0402
  round 0.635 smd: 1(-0.508,0) 2(0.508,0)
SM-7351-CAP-0603
  rect 1.092x1.041 smd: 1(-0.85,0) 2(0.85,0)
SM-7351-CAP-0805
  rect 1.346x1.524 smd: 1(-1,0) 2(1,0)
SM-7351-CAP-1206
  rect 1.2x1.85 smd: 1(1.6,0) 2(-1.6,0)
SM-7351-CAP-2917
  rect 2.413x2.54 smd: 1(3.175,0) 2(-3.175,0)
SM-7351-CAP-SMDCAN
  rect 4.15x1.65 smd: 1(3.05,0) 2(-3.05,0)
SM-7351-IND-0603
  rect 1.143x1.092 smd: 1(-0.9,0) 2(0.9,0)
SM-7351-IND-0805
  rect 1.397x1.549 smd: 1(-0.95,0) 2(0.95,0)
SM-7351-RES-0402
  round 0.635 smd: 1(-0.508,0) 2(0.508,0)
SM-7351-RES-0603
  rect 1.143x1.092 smd: 1(-0.9,0) 2(0.9,0)
SM-SO-SC70-5
  rect 0.406x1.016 smd: 1(-0.65,-0.95) 2(0,-0.95) 3(0.65,-0.95) 4(0.65,0.95) 5(-0.65,0.95)
SM_LED_0805
  rect 1.15x1.194 smd: 1(1.125,0) 2(-1.125,0)
SM_OSC_ABM3
  rect 1.9x2.4 smd: 1(-2.05,0) 2(2.05,0)
SM_RES_LVK12
  rect 1.75x1.1 smd: 1(-1.375,0.7) 2(1.375,0.7) 3(-1.375,-0.7) 4(1.375,-0.7)
SMCJ26CA
  rect 2.6x3.2 smd: 1(-3.6,0) 2(3.6,0)
SMD15X11-6-374M
  rect 1.2x1.8 smd: 1(-5.08,-5.1) 2(-2.54,-5.1) 4(2.54,-5.1) 5(5.08,-5.1) 7(2.54,5.1) 10(-5.08,5.1)
SMD_HDMIA_RA
  rect 0.3x1.9 smd: 1(4.75,4.925) 2(4.25,4.925) 3(3.75,4.925) 4(3.25,4.925) 5(2.75,4.925) 6(2.25,4.925) 7(1.75,4.925) 8(1.25,4.925) 9(0.75,4.925) 10(0.25,4.925) 11(-0.25,4.925) 12(-0.75,4.925) 13(-1.25,4.925) 14(-1.75,4.925) 15(-2.25,4.925) 16(-2.75,4.925) 17(-3.25,4.925) 18(-3.75,4.925) 19(-4.25,4.925)
  round 1.778 hole 1.27: MTG1(-7.25,3.925) MTG2(7.25,3.925) MTG3(-7.85,-0.975) MTG4(7.85,-0.975)
SMD_SLF7055T
  rect 1.5x2.2 smd: 1(-3.15,0) 2(3.15,0)
SMDSC70-5
  rect 0.406x1.016 smd: 1(-0.65,-0.95) 2(0,-0.95) 3(0.65,-0.95) 4(0.65,0.95) 5(-0.65,0.95)
SO9X6-8-191M
  rect 0.813x2.997 smd: 1(-3.81,-4.8) 2(-1.27,-4.8) 3(1.27,-4.8) 4(3.81,-4.8) 5(3.81,4.8) 6(1.27,4.8) 7(-1.27,4.8) 8(-3.81,4.8)
SOD-123
  rect 0.914x1.219 smd: 1(1.651,0) 2(-1.651,0)
SOIC_8
  rect 0.61x2.184 smd: 1(-1.905,-2.603)
  oval 0.61x2.184 smd: 2(-0.635,-2.603) 3(0.635,-2.603) 4(1.905,-2.603) 5(1.905,2.603) 6(0.635,2.603) 7(-0.635,2.603) 8(-1.905,2.603)
SOIC_16PIN_DW
  rect 0.6x2 smd: 1(-4.445,-4.7) 2(-3.175,-4.7) 3(-1.905,-4.7) 4(-0.635,-4.7) 5(0.635,-4.7) 6(1.905,-4.7) 7(3.175,-4.7) 8(4.445,-4.7) 9(4.445,4.7) 10(3.175,4.7) 11(1.905,4.7) 12(0.635,4.7) 13(-0.635,4.7) 14(-1.905,4.7) 15(-3.175,4.7) 16(-4.445,4.7)
SON2X1-8-16M
  rect 0.85x0.2 smd: 1(-0.55,0.6) 2(-0.55,0.2) 3(-0.55,-0.2) 4(-0.55,-0.6) 5(0.55,-0.6) 6(0.55,-0.2) 7(0.55,0.2) 8(0.55,0.6)
SOT1X1-3-20M
  rect 0.55x0.3 smd: 1(-0.575,0.35) 2(-0.575,-0.35) 3(0.575,0)
SOT23-3
  rect 0.787x0.889 smd: D(0,1.003) G(-0.94,-1.003) S(0.94,-1.003)
SOT23-3-44M
  rect 0.6x1.05 smd: 1(-0.95,-1.185) 2(0.95,-1.185) 3(0,1.185)
SOT223-4
  rect 2.2x1.2 smd: D1(-2.95,0) G(-2.95,2.3) S(-2.95,-2.3)
  rect 2.2x3.2 smd: D2(2.95,0)
SOT-223-5
  rect 1.5x1 smd: 1(-3.15,2.25) 2(-3.15,0.75) 3(-3.15,-0.75) 4(-3.15,-2.25)
  rect 1.5x3.3 smd: 5(3.15,0)
SW_B3SL-1022P
  rect 2.75x1 smd: 1(2.875,-2) 2(-2.875,-2) 3(2.875,2) 4(-2.875,2)
TH_TP_5002
  round 1.778 hole 1.016: 1(0,0)
TP_SMD1MMCIRCLE
  round 1.016 smd: 1(0,0)
TPD1E10B06-2L
  rect 0.6x0.5 smd: 1(-0.5,0) 2(0.5,0)
TSSOP5X4-14-47M
  rect 1.4x0.4 smd: 1(-2.95,1.95) 2(-2.95,1.3) 3(-2.95,0.65) 4(-2.95,0) 5(-2.95,-0.65) 6(-2.95,-1.3) 7(-2.95,-1.95) 8(2.95,-1.95) 9(2.95,-1.3) 10(2.95,-0.65) 11(2.95,0) 12(2.95,0.65) 13(2.95,1.3) 14(2.95,1.95)
U_5_DCK
  rect 0.432x1.27 smd: 1(0.65,0.775) 2(0,0.775) 3(-0.65,0.775) 4(-0.65,-0.884) 5(0.65,-0.884)
U_5_DRL
  rect 0.3x0.45 smd: 1(-0.5,-0.675) 2(0,-0.675) 3(0.5,-0.675) 4(0.5,0.675) 5(-0.5,0.675)
U_6_DRY
  rect 0.305x0.508 smd: 1(-0.5,-0.379) 2(0,-0.379) 3(0.5,-0.379) 4(0.5,0.379) 5(0,0.379) 6(-0.5,0.379)
U_8_D
  rect 0.6x2 smd: 1(-1.905,-2.4) 2(-0.635,-2.4) 3(0.635,-2.4) 4(1.905,-2.4) 5(1.905,2.4) 6(0.635,2.4) 7(-0.635,2.4) 8(-1.905,2.4)
U_10_DRC
  rect 0.28x0.85 smd: 1(-1,-1.475) 2(-0.5,-1.475) 3(0,-1.475) 4(0.5,-1.475) 5(1,-1.475) 6(1,1.475) 7(0.5,1.475) 8(0,1.475) 9(-0.5,1.475) 10(-1,1.475)
  custom 0.412x0.412 smd: PAD(0,0)
U_10_RSE
  rect 0.3x0.58 smd: 1(-0.75,-0.635) 2(-0.25,-0.635) 3(0.25,-0.635) 4(0.75,-0.635) 6(0.75,0.635) 7(0.25,0.635) 8(-0.25,0.635) 9(-0.75,0.635)
  rect 0.63x0.35 smd: 5(0.86,0) 10(-0.86,0)
U_16_D
  rect 0.6x2 smd: 1(-4.445,-2.4) 2(-3.175,-2.4) 3(-1.905,-2.4) 4(-0.635,-2.4) 5(0.635,-2.4) 6(1.905,-2.4) 7(3.175,-2.4) 8(4.445,-2.4) 9(4.445,2.4) 10(3.175,2.4) 11(1.905,2.4) 12(0.635,2.4) 13(-0.635,2.4) 14(-1.905,2.4) 15(-3.175,2.4) 16(-4.445,2.4)
U_16_DW
  rect 0.6x2 smd: 1(-4.445,-4.7) 2(-3.175,-4.7) 3(-1.905,-4.7) 4(-0.635,-4.7) 5(0.635,-4.7) 6(1.905,-4.7) 7(3.175,-4.7) 8(4.445,-4.7) 9(4.445,4.7) 10(3.175,4.7) 11(1.905,4.7) 12(0.635,4.7) 13(-0.635,4.7) 14(-1.905,4.7) 15(-3.175,4.7) 16(-4.445,4.7)
U_16_PW
  rect 0.35x1.6 smd: 1(-2.275,-2.8) 2(-1.625,-2.8) 3(-0.975,-2.8) 4(-0.325,-2.8) 5(0.325,-2.8) 6(0.975,-2.8) 7(1.625,-2.8) 8(2.275,-2.8) 9(2.275,2.8) 10(1.625,2.8) 11(0.975,2.8) 12(0.325,2.8) 13(-0.325,2.8) 14(-0.975,2.8) 15(-1.625,2.8) 16(-2.275,2.8)
U_20_DSBGA
  round 0.254 smd: A1(0.6,-0.8) A2(0.2,-0.8) A3(-0.2,-0.8) A4(-0.6,-0.8) B1(0.6,-0.4) B2(0.2,-0.4) B3(-0.2,-0.4) B4(-0.6,-0.4) C1(0.6,0) C2(0.2,0) C3(-0.2,0) C4(-0.6,0) D1(0.6,0.4) D2(0.2,0.4) D3(-0.2,0.4) D4(-0.6,0.4) E1(0.6,0.8) E2(0.2,0.8) E3(-0.2,0.8) E4(-0.6,0.8)
U_28_PWP
  rect 0.3x1.45 smd: 1(-4.225,-2.8) 2(-3.575,-2.8) 3(-2.925,-2.8) 4(-2.275,-2.8) 5(-1.625,-2.8) 6(-0.975,-2.8) 7(-0.325,-2.8) 8(0.325,-2.8) 9(0.975,-2.8) 10(1.625,-2.8) 11(2.275,-2.8) 12(2.925,-2.8) 13(3.575,-2.8) 14(4.225,-2.8) 15(4.225,2.8) 16(3.575,2.8) 17(2.925,2.8) 18(2.275,2.8) 19(1.625,2.8) 20(0.975,2.8) 21(0.325,2.8) 22(-0.325,2.8) 23(-0.975,2.8) 24(-1.625,2.8) 25(-2.275,2.8) 26(-2.925,2.8) 27(-3.575,2.8) 28(-4.225,2.8)
  rect 9.7x3.4 smd: TH_PD(0,0)
unnamed#2
  round 3.505 hole 3.505 unplated: (0,0)
unnamed#3
  round 1.016 smd: 1(0,0)
USON2X1-10-22M
  rect 0.55x0.3 smd: 1(-0.385,1) 2(-0.385,0.5) 4(-0.385,-0.5) 5(-0.385,-1) 6(0.385,-1) 7(0.385,-0.5) 9(0.385,0.5) 10(0.385,1)
  rect 0.55x0.4 smd: 3(-0.385,0) 8(0.385,0)
VLCF5020T
  custom 0.525x0.525 smd: 1(-1.7,0) 2(1.7,0)
X2SON1X1-4-16M
  custom 0.088x0.088 smd: 1(-0.455,0.325) 2(-0.525,-0.325) 3(0.525,-0.325) 4(0.525,0.325)
  rect 0.58x0.58 smd rot 45: TPAD(0,0)
XTAL2X3-30M
  rect 1.15x1.4 smd: 1(-0.8,1.2) 2(-0.8,-1.2) 3(0.8,-1.2) 4(0.8,1.2)
XTAL3225-39M
  rect 1.4x1.2 smd: 1(-1.1,-0.85) 2(1.1,-0.85) 3(1.1,0.85) 4(-1.1,0.85)
ZX62-AB-5PA
  rect 1.9x1.9 smd: (-1.2,-2.675) (1.2,-2.675)
  rect 0.4x1.35 smd: 1(-1.3,0) 2(-0.65,0) 3(0,0) 4(0.65,0) 5(1.3,0)
  rect 2.1x1.6 smd: S1(-3.1,-0.125) S2(3.1,-0.125)
  rect 1.8x1.9 smd: S3(-4.1,-2.675) S4(4.1,-2.675)

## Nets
AGND_GBETH0: C166.2 C167.2 J10.SHLD1 J10.SHLD2
AGND_GBETH1: C187.2 C188.2 J12.SHLD1 J12.SHLD2
AGND_PROFI: J14.10 J14.11 R573.2(P2)
AGNDFRAME_PRU1ETH0: C106.2 J3.SHLD1 J3.SHLD2
AGNDFRAME_PRU1ETH1: C121.2 J5.SHLD1 J5.SHLD2
AGNDFRAME_PRU2ETH0: C131.2 J6.SHLD1 J6.SHLD2
AGNDFRAME_PRU2ETH1: C146.2 J8.SHLD1 J8.SHLD2
